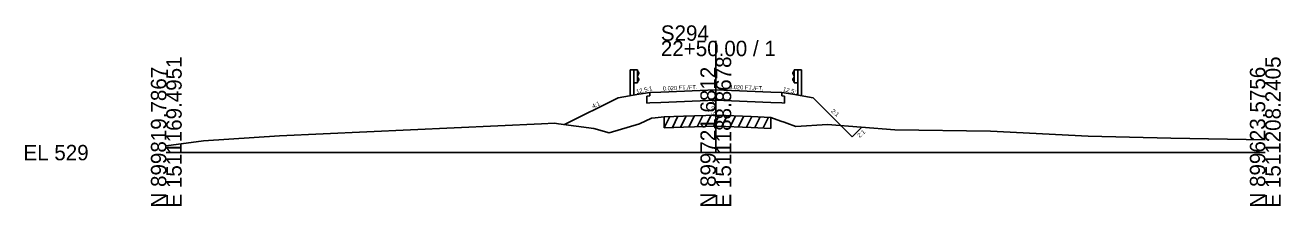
# Model space of a CAD drawing. Extents: x 974 to 2203, y -10 to 19041.
# Drawn here: x 1974.3 to 2202.8, y 4990.3 to 5023.2 of the extents above; entities that cross this region are included whole.
import ezdxf

# ---------------------------------------------------------------- set-up
doc = ezdxf.new("R2010")
doc.units = 0
for name, color, linetype in [('RD_GPK_XS_Cell', 7, 'Continuous'), ('RD_XS_Base', 7, 'Continuous'), ('RD_XS_EarthShd', 7, 'Continuous'), ('RD_XS_ExGround', 7, 'Continuous'), ('RD_XS_ExPaveRet', 7, 'Continuous'), ('RD_XS_GR', 7, 'Continuous'), ('RD_XS_Pave', 7, 'Continuous'), ('RD_XS_TX_Elev_EX', 7, 'Continuous'), ('RD_XS_TX_Slope', 7, 'Continuous')]:
    doc.layers.add(name, color=color, linetype=linetype)

msp = doc.modelspace()

# ---------------------------------------------------------------- linework, layer by layer
at = {"layer": 'RD_GPK_XS_Cell'}
for p, q in [((2100, 5000), (2100, 5020.34)), ((2000, 5000), (2100, 5000)), ((2100, 5000), (2200, 5000))]:
    msp.add_line(p, q, dxfattribs=at)
at = {"layer": 'RD_XS_Base'}
for p, q in [((2088, 5010.3), (2087.48, 5010.28)), ((2087.48, 5009.01), (2087.48, 5010.28)), ((2088, 5010.3), (2088, 5010.94)), ((2090, 5009.11), (2100, 5009.51)), ((2110, 5009.11), (2100, 5009.51)), ((2112, 5010.3), (2112, 5010.94)), ((2112, 5010.3), (2112.52, 5010.28)), ((2112.52, 5009.01), (2112.52, 5010.28)), ((2087.98, 5009.03), (2087.48, 5009.01)), ((2087.98, 5009.03), (2090, 5009.11)), ((2112.02, 5009.03), (2110, 5009.11)), ((2112.02, 5009.03), (2112.52, 5009.01))]:
    msp.add_line(p, q, dxfattribs=at)
at = {"layer": 'RD_XS_EarthShd'}
for p, q in [((2082.25, 5009.98), (2072.47, 5005.09)), ((2086, 5010.61), (2082.25, 5009.98)), ((2088, 5010.94), (2086, 5010.61)), ((2112, 5010.94), (2114, 5010.61)), ((2114, 5010.61), (2117.75, 5009.98)), ((2124.84, 5002.89), (2117.75, 5009.98)), ((2124.84, 5002.89), (2126.56, 5004.61))]:
    msp.add_line(p, q, dxfattribs=at)
at = {"layer": 'RD_XS_ExGround'}
msp.add_lwpolyline([(2000, 5001.23), (2006.8, 5002.16), (2020.63, 5003.07), (2068.31, 5005.25), (2070.62, 5005.37), (2071.36, 5005.24), (2077.8, 5004.39), (2080.6, 5003.59), (2086.11, 5005.24), (2088.29, 5006.26), (2088.97, 5006.34), (2090.6, 5006.52), (2094.15, 5006.64), (2100.2, 5006.78), (2106.42, 5006.58), (2110.01, 5006.41), (2111.86, 5005.72), (2112.46, 5005.51), (2112.95, 5005.36), (2114.58, 5004.76), (2120.33, 5005.08), (2132.57, 5004.15), (2150, 5003.9), (2167.78, 5003.01), (2182.82, 5002.62), (2200, 5002.34)], dxfattribs=at)
at = {"layer": 'RD_XS_ExPaveRet'}
for p, q in [((2090.6, 5004.52), (2091.62, 5006.55)), ((2090.6, 5004.52), (2090.6, 5006.52)), ((2092.1, 5004.57), (2093.12, 5006.6)), ((2093.6, 5004.62), (2094.62, 5006.65)), ((2095.1, 5004.66), (2096.12, 5006.68)), ((2096.6, 5004.69), (2097.62, 5006.72)), ((2098.1, 5004.73), (2099.12, 5006.75)), ((2099.6, 5004.77), (2100.6, 5006.77)), ((2101.1, 5004.75), (2102.09, 5006.72)), ((2102.6, 5004.7), (2103.59, 5006.67)), ((2104.1, 5004.65), (2105.09, 5006.62)), ((2105.6, 5004.6), (2106.59, 5006.57)), ((2107.1, 5004.55), (2108.08, 5006.5)), ((2108.6, 5004.48), (2109.58, 5006.43)), ((2110.01, 5006.41), (2110.01, 5004.41)), ((2090.6, 5004.52), (2094.15, 5004.64)), ((2094.15, 5004.64), (2100.2, 5004.78)), ((2100.2, 5004.78), (2106.42, 5004.58)), ((2106.42, 5004.58), (2110.01, 5004.41))]:
    msp.add_line(p, q, dxfattribs=at)
at = {"layer": 'RD_XS_GR'}
for p, q in [((2084.4, 5015.03), (2084.4, 5010.26)), ((2085.06, 5015.03), (2084.4, 5015.03)), ((2085.06, 5015.03), (2085.06, 5010.37)), ((2085.73, 5015.03), (2085.06, 5015.03)), ((2085.73, 5012.69), (2085.73, 5015.03)), ((2085.73, 5014.88), (2086, 5014.48)), ((2086, 5014.38), (2085.73, 5013.98)), ((2086, 5014.48), (2086, 5014.38)), ((2114.27, 5014.88), (2114, 5014.48)), ((2114, 5014.48), (2114, 5014.38)), ((2114, 5014.38), (2114.27, 5013.98)), ((2114.27, 5015.03), (2114.94, 5015.03)), ((2114.27, 5012.69), (2114.27, 5015.03)), ((2114.94, 5015.03), (2114.94, 5010.37)), ((2114.94, 5015.03), (2115.6, 5015.03)), ((2115.6, 5015.03), (2115.6, 5010.26)), ((2085.73, 5012.69), (2085.06, 5012.69)), ((2086, 5013.34), (2085.73, 5013.74)), ((2085.73, 5012.84), (2086, 5013.24)), ((2086, 5013.24), (2086, 5013.34)), ((2114, 5013.34), (2114.27, 5013.74)), ((2114, 5013.24), (2114, 5013.34)), ((2114.27, 5012.84), (2114, 5013.24)), ((2114.27, 5012.69), (2114.94, 5012.69))]:
    msp.add_line(p, q, dxfattribs=at)
at = {"layer": 'RD_XS_Pave'}
for p, q in [((2088, 5010.94), (2090, 5011.02)), ((2090, 5011.02), (2100, 5011.42)), ((2110, 5011.02), (2100, 5011.42)), ((2112, 5010.94), (2110, 5011.02))]:
    msp.add_line(p, q, dxfattribs=at)

# ---------------------------------------------------------------- texts
at = {"layer": 'RD_GPK_XS_Cell'}
for s, p in [('S294', (2090, 5020.34)), ('22+50.00 / 1', (2090, 5017.54)), ('EL 529', (1974, 4998.6))]:
    msp.add_text(s, height=2.8, dxfattribs=at).set_placement(p)
for s, p in [('E 1511169.4951', (2002.8, 4990)), ('E 1511188.8678', (2102.8, 4990)), ('E 1511208.2405', (2202.8, 4990)), ('N 899819.7867', (2000, 4990)), ('N 899721.6812', (2100, 4990)), ('N 899623.5756', (2200, 4990))]:
    msp.add_text(s, height=2.8, rotation=90, dxfattribs=at).set_placement(p)
at = {"layer": 'RD_XS_TX_Elev_EX'}
msp.add_text('532.39', height=0.75, rotation=90, dxfattribs=at).set_placement((2100, 5006.78))
at = {"layer": 'RD_XS_TX_Slope'}
for s, height, rotation, p in [('12.5:1', 0.778, 12.7511, (2085.61, 5010.69)), ('0.020 FT./FT.', 0.7518, 2.396, (2090.38, 5011.28)), ('0.020 FT./FT.', 0.7518, 357.604, (2102.4, 5011.58)), ('12.5:1', 0.778, 347.2489, (2112.17, 5011.19)), ('4:1', 0.778, 26.3688, (2077.69, 5008.02)), ('2:1', 0.778, 319.3411, (2120.92, 5007.44)), ('2:1', 0.778, 40.6589, (2126.18, 5002.67))]:
    msp.add_text(s, height=height, rotation=rotation, dxfattribs=at).set_placement(p)

doc.saveas('drawing.dxf')
